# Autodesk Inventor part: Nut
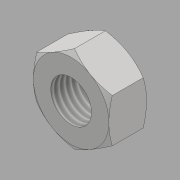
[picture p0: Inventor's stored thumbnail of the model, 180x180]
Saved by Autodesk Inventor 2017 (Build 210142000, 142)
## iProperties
Created: 2016-05
Part Number: Nut
Material: Generic
Document SubType Name: Modeling
Designer: CADCIM
Density: 1 g/cm^3
Appearance: Default
Author: CADCIM
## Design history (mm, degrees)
sketch "Sketch1"
  geometry: L1 (0, -18.475)-(-16, -9.238); L2 (-16, -9.238)-(-16, 9.238); L3 (-16, 9.238)-(0, 18.475); L4 (0, 18.475)-(16, 9.238); L5 (16, 9.238)-(16, -9.238); L6 (16, -9.238)-(0, -18.475); 2 further points
  constraints: 12 end point, 1 coincident, 13 other
  dimensions: "d0" = 32 distance between parallel lines of L2 L5
extrude "Extrusion1" new body sketch "Sketch1" distance "d1" = 16; taper "d2" = 0 deg
sketch "Sketch2"
  geometry: L1 (16, -9.238)-(16, 9.238) reference; C1 r 16 at (0, 0); 1 further point
  constraints: 1 centre point, 1 coincident, 1 tangent
extrude "Extrusion2" sketch "Sketch2" distance "d3" = 16; taper "d4" = 60 deg
sketch "Sketch3"
  geometry: L1 (0, -18.475)-(16, -9.238) reference; C1 r 16 at (0, 0); 1 further point
  constraints: 1 centre point, 1 coincident, 1 tangent
extrude "Extrusion3" sketch "Sketch3" distance "d5" = 16; taper "d6" = 60 deg
hole "Hole1" diameter "d9" = 17.294; stored, may be unused: countersink angle "d13" = 90 deg, drill point angle "d15" = 118 deg; dims "d7" = 10, "d8" = 10, "d10" = 40, "d11" = 4, "d12" = 2, "d14" = 51.2
body "Solid1"
